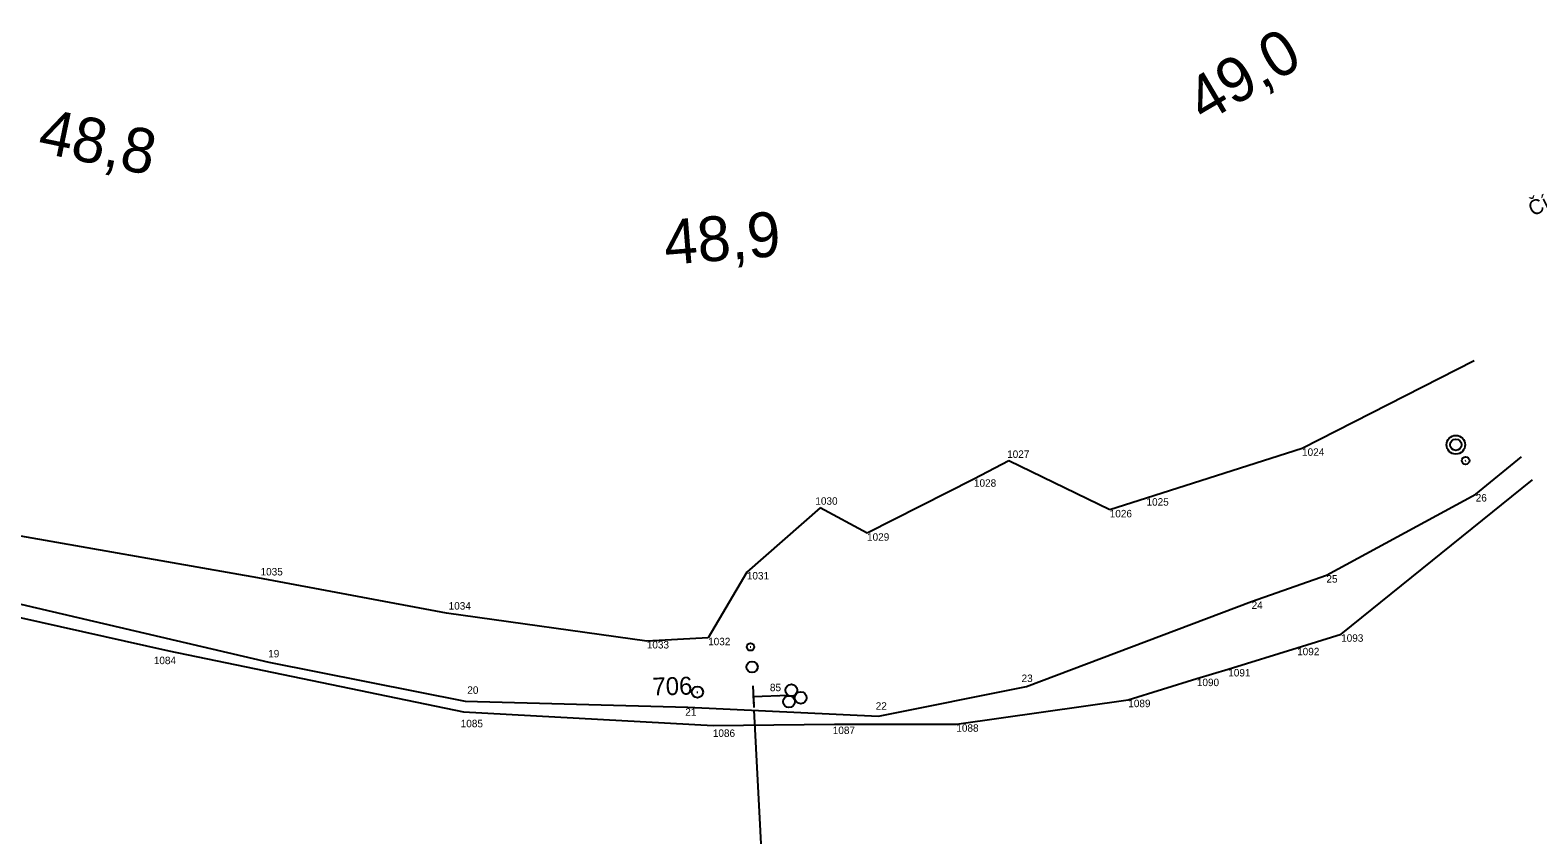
# Model space of a CAD drawing. Extents: x -679938 to -678300, y -1007495 to -1006487.
# Drawn here: x -678711.9 to -678510.1, y -1006847.2 to -1006739.4 of the extents above; entities that cross this region are included whole.
import ezdxf

# ---------------------------------------------------------------- set-up
doc = ezdxf.new("R2010")
doc.units = 0
for name, color, linetype in [('Default', 7, 'Continuous'), ('SSZT nové - lomové body', 7, 'Continuous'), ('SSZT_nové', 7, 'Continuous'), ('Stávající ŽBP', 7, 'Continuous'), ('SŽDC', 7, 'Continuous'), ('SŽDC - body', 7, 'Continuous'), ('Vrstva 7', 7, 'Continuous')]:
    doc.layers.add(name, color=color, linetype=linetype)

msp = doc.modelspace()

# ---------------------------------------------------------------- linework, layer by layer
at = {"layer": 'SSZT nové - lomové body'}
for p, q in [((-678518.43, -1006801.56), (-678518.43, -1006801.56)), ((-678538.41, -1006812.42), (-678538.41, -1006812.42)), ((-678548.42, -1006815.94), (-678548.42, -1006815.94)), ((-678679.95, -1006824.06), (-678679.95, -1006824.06)), ((-678578.56, -1006827.33), (-678578.56, -1006827.33)), ((-678653.68, -1006829.31), (-678653.68, -1006829.31)), ((-678611.84, -1006828.42), (-678611.84, -1006828.42)), ((-678623.86, -1006830.09), (-678623.86, -1006830.09)), ((-678598.34, -1006831.32), (-678598.34, -1006831.32))]:
    msp.add_line(p, q, dxfattribs=at)
at = {"layer": 'SSZT_nové'}
for p, q in [((-678615.18, -1006827.26), (-678615.03, -1006830.16)), ((-678610.38, -1006828.54), (-678615.11, -1006828.73)), ((-678615.11, -1006828.71), (-678615.04, -1006829.61)), ((-678615.06, -1006830.49), (-678613.33, -1006862.53))]:
    msp.add_line(p, q, dxfattribs=at)
msp.add_lwpolyline([(-678758.68, -1006808.66), (-678745.48, -1006809.62), (-678725.58, -1006813.41), (-678679.95, -1006824.06), (-678653.68, -1006829.31), (-678623.86, -1006830.09), (-678598.34, -1006831.32), (-678578.56, -1006827.33), (-678548.42, -1006815.94), (-678538.41, -1006812.42), (-678518.43, -1006801.56), (-678512.32, -1006796.58)], dxfattribs=at)
for centre in [(-678610.02, -1006827.83), (-678610.34, -1006829.36), (-678608.77, -1006828.84)]:
    msp.add_circle(centre, 0.792, dxfattribs=at)
at = {"layer": 'Stávající ŽBP'}
msp.add_line((-678622.65, -1006828.08), (-678622.55, -1006828.08), dxfattribs=at)
msp.add_circle((-678622.6, -1006828.08), 0.756, dxfattribs=at)
at = {"layer": 'SŽDC'}
for p, q in [((-678518.63, -1006783.74), (-678541.67, -1006795.44)), ((-678580.93, -1006797.11), (-678585.58, -1006799.58)), ((-678567.41, -1006803.68), (-678580.93, -1006797.11)), ((-678541.67, -1006795.44), (-678562.49, -1006802.11)), ((-678681.43, -1006812.76), (-678748.44, -1006800.99)), ((-678585.58, -1006799.58), (-678599.89, -1006806.81)), ((-678536.44, -1006820.34), (-678510.81, -1006799.64)), ((-678606.18, -1006803.39), (-678615.98, -1006812)), ((-678599.89, -1006806.81), (-678606.18, -1006803.39)), ((-678562.49, -1006802.11), (-678567.41, -1006803.68)), ((-678734.16, -1006813.39), (-678693.35, -1006822.57)), ((-678656.18, -1006817.5), (-678681.43, -1006812.76)), ((-678615.98, -1006812), (-678621.16, -1006820.81)), ((-678629.37, -1006821.24), (-678656.18, -1006817.5)), ((-678621.16, -1006820.81), (-678629.37, -1006821.24)), ((-678542.33, -1006822.15), (-678536.44, -1006820.34)), ((-678693.35, -1006822.57), (-678653.9, -1006830.72)), ((-678551.55, -1006824.99), (-678542.33, -1006822.15)), ((-678555.75, -1006826.28), (-678551.55, -1006824.99)), ((-678564.93, -1006829.1), (-678555.75, -1006826.28)), ((-678587.94, -1006832.39), (-678564.93, -1006829.1)), ((-678653.9, -1006830.72), (-678620.49, -1006832.57)), ((-678620.49, -1006832.57), (-678604.23, -1006832.39)), ((-678604.23, -1006832.39), (-678587.94, -1006832.39))]:
    msp.add_line(p, q, dxfattribs=at)
at = {"layer": 'SŽDC - body'}
for p, q in [((-678580.93, -1006797.11), (-678580.93, -1006797.11)), ((-678541.67, -1006795.44), (-678541.67, -1006795.44)), ((-678585.58, -1006799.58), (-678585.58, -1006799.58)), ((-678606.18, -1006803.39), (-678606.18, -1006803.39)), ((-678562.49, -1006802.11), (-678562.49, -1006802.11)), ((-678567.41, -1006803.68), (-678567.41, -1006803.68)), ((-678599.89, -1006806.81), (-678599.89, -1006806.81)), ((-678681.43, -1006812.76), (-678681.43, -1006812.76)), ((-678615.98, -1006812), (-678615.98, -1006812)), ((-678656.18, -1006817.5), (-678656.18, -1006817.5)), ((-678629.37, -1006821.24), (-678629.37, -1006821.24)), ((-678621.16, -1006820.81), (-678621.16, -1006820.81)), ((-678536.44, -1006820.34), (-678536.44, -1006820.34)), ((-678693.35, -1006822.57), (-678693.35, -1006822.57)), ((-678542.33, -1006822.15), (-678542.33, -1006822.15)), ((-678551.55, -1006824.99), (-678551.55, -1006824.99)), ((-678555.75, -1006826.28), (-678555.75, -1006826.28)), ((-678564.93, -1006829.1), (-678564.93, -1006829.1)), ((-678653.9, -1006830.72), (-678653.9, -1006830.72)), ((-678620.49, -1006832.57), (-678620.49, -1006832.57)), ((-678604.23, -1006832.39), (-678604.23, -1006832.39)), ((-678587.94, -1006832.39), (-678587.94, -1006832.39))]:
    msp.add_line(p, q, dxfattribs=at)
at = {"layer": 'Vrstva 7'}
for p, q in [((-678519.82, -1006797.1), (-678519.73, -1006797.05)), ((-678615.54, -1006822.03), (-678615.44, -1006822.02))]:
    msp.add_line(p, q, dxfattribs=at)
for centre, radius in [((-678521.09, -1006794.96), 1.25), ((-678521.09, -1006794.96), 0.752), ((-678519.78, -1006797.08), 0.5), ((-678615.49, -1006822.03), 0.5), ((-678615.27, -1006824.72), 0.75)]:
    msp.add_circle(centre, radius, dxfattribs=at)

# ---------------------------------------------------------------- texts
at = {"layer": 'Default'}
msp.add_text('Číslo ověření:', height=2, rotation=26.2093, dxfattribs=at).set_placement((-678510.78, -1006764.42))
at = {"layer": 'SSZT nové - lomové body'}
for s, p in [('26', (-678518.43, -1006802.56)), ('25', (-678538.41, -1006813.42)), ('24', (-678548.42, -1006816.94)), ('19', (-678680.04, -1006823.43)), ('20', (-678653.39, -1006828.31)), ('85', (-678612.89, -1006827.96)), ('23', (-678579.21, -1006826.73)), ('22', (-678598.73, -1006830.44)), ('21', (-678624.22, -1006831.24))]:
    msp.add_text(s, height=1, dxfattribs=at).set_placement(p)
at = {"layer": 'Stávající ŽBP'}
msp.add_text('706', height=2.4, rotation=1.5337, dxfattribs=at).set_placement((-678628.59, -1006828.55))
at = {"layer": 'SŽDC - body'}
for s, p in [('1027', (-678581.14, -1006796.72)), ('1024', (-678541.67, -1006796.44)), ('1028', (-678585.58, -1006800.58)), ('1030', (-678606.81, -1006802.99)), ('1025', (-678562.49, -1006803.11)), ('1026', (-678567.41, -1006804.68)), ('1029', (-678599.89, -1006807.81)), ('1035', (-678681.06, -1006812.46)), ('1031', (-678615.98, -1006813)), ('1034', (-678655.89, -1006817.03)), ('1033', (-678629.37, -1006822.24)), ('1032', (-678621.16, -1006821.81)), ('1093', (-678536.44, -1006821.34)), ('1084', (-678695.35, -1006824.34)), ('1092', (-678542.33, -1006823.15)), ('1091', (-678551.55, -1006825.99)), ('1090', (-678555.75, -1006827.28)), ('1089', (-678564.93, -1006830.1)), ('1085', (-678654.27, -1006832.79)), ('1086', (-678620.53, -1006834.08)), ('1087', (-678604.48, -1006833.7)), ('1088', (-678587.94, -1006833.39))]:
    msp.add_text(s, height=1, dxfattribs=at).set_placement(p)
at = {"layer": 'Vrstva 7'}
for s, rotation, p in [('49,0', 30.5229, (-678554.77, -1006751.98)), ('48,8', 348.3028, (-678711.07, -1006755.73)), ('48,9', 4.5291, (-678626.84, -1006770.88))]:
    msp.add_text(s, height=6, rotation=rotation, dxfattribs=at).set_placement(p)

doc.saveas('drawing.dxf')
